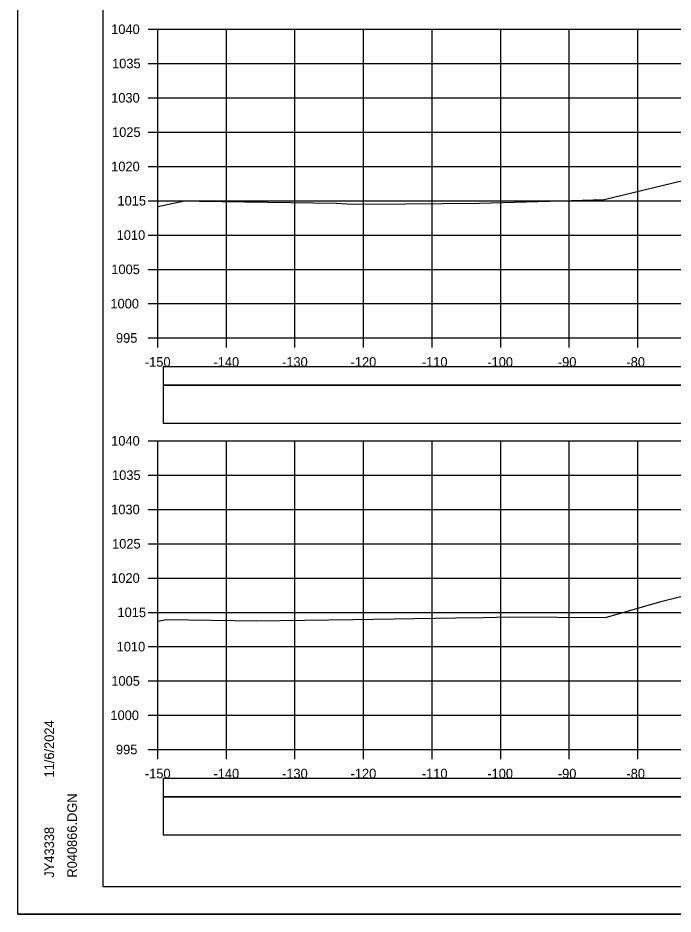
# Model space of a CAD drawing. Extents: x 1370565 to 1374448, y 301010 to 304637.
# Drawn here: x 1370564.6 to 1370660.2, y 302503.9 to 302634.5 of the extents above; entities that cross this region are included whole.
import ezdxf

# ---------------------------------------------------------------- set-up
doc = ezdxf.new("R2010")
doc.units = 0
for name, color, linetype in [('R_Axis', 7, 'Continuous'), ('R_Axis Annot', 7, 'Continuous'), ('R_Border', 7, 'Continuous'), ('R_Drive', 7, 'Continuous'), ('R_Exist Surface', 7, 'Continuous'), ('R_Grid', 7, 'Continuous'), ('R_No Plot', 7, 'Continuous')]:
    doc.layers.add(name, color=color, linetype=linetype)

msp = doc.modelspace()

# ---------------------------------------------------------------- linework, layer by layer
at = {"layer": 'R_Axis'}
for p, q in [((1370583.63, 302632.84), (1370585.03, 302632.84)), ((1370585.03, 302587.84), (1370585.03, 302632.84)), ((1370583.63, 302627.84), (1370585.03, 302627.84)), ((1370583.63, 302622.84), (1370585.03, 302622.84)), ((1370583.63, 302617.84), (1370585.03, 302617.84)), ((1370583.63, 302612.84), (1370585.03, 302612.84)), ((1370583.63, 302607.84), (1370585.03, 302607.84)), ((1370583.63, 302602.84), (1370585.03, 302602.84)), ((1370583.63, 302597.84), (1370585.03, 302597.84)), ((1370583.63, 302592.84), (1370585.03, 302592.84)), ((1370583.63, 302587.84), (1370585.03, 302587.84)), ((1370585.03, 302587.84), (1370885.03, 302587.84)), ((1370585.03, 302586.44), (1370585.03, 302587.84)), ((1370595.03, 302586.44), (1370595.03, 302587.84)), ((1370605.03, 302586.44), (1370605.03, 302587.84)), ((1370615.03, 302586.44), (1370615.03, 302587.84)), ((1370625.03, 302586.44), (1370625.03, 302587.84)), ((1370635.03, 302586.44), (1370635.03, 302587.84)), ((1370645.03, 302586.44), (1370645.03, 302587.84)), ((1370655.03, 302586.44), (1370655.03, 302587.84)), ((1370583.63, 302572.84), (1370585.03, 302572.84)), ((1370585.03, 302527.84), (1370585.03, 302572.84)), ((1370583.63, 302567.84), (1370585.03, 302567.84)), ((1370583.63, 302562.84), (1370585.03, 302562.84)), ((1370583.63, 302557.84), (1370585.03, 302557.84)), ((1370583.63, 302552.84), (1370585.03, 302552.84)), ((1370583.63, 302547.84), (1370585.03, 302547.84)), ((1370583.63, 302542.84), (1370585.03, 302542.84)), ((1370583.63, 302537.84), (1370585.03, 302537.84)), ((1370583.63, 302532.84), (1370585.03, 302532.84)), ((1370583.63, 302527.84), (1370585.03, 302527.84)), ((1370585.03, 302527.84), (1370885.03, 302527.84)), ((1370585.03, 302526.44), (1370585.03, 302527.84)), ((1370595.03, 302526.44), (1370595.03, 302527.84)), ((1370605.03, 302526.44), (1370605.03, 302527.84)), ((1370615.03, 302526.44), (1370615.03, 302527.84)), ((1370625.03, 302526.44), (1370625.03, 302527.84)), ((1370635.03, 302526.44), (1370635.03, 302527.84)), ((1370645.03, 302526.44), (1370645.03, 302527.84)), ((1370655.03, 302526.44), (1370655.03, 302527.84))]:
    msp.add_line(p, q, dxfattribs=at)
at = {"layer": 'R_Border'}
for p, q in [((1370577.03, 302507.84), (1370577.03, 302713.3)), ((1370577.03, 302507.84), (1370577.03, 302507.84)), ((1370893.21, 302507.84), (1370577.03, 302507.84))]:
    msp.add_line(p, q, dxfattribs=at)
at = {"layer": 'R_Drive'}
for points in [[(1370585.82, 302580.94), (1370884.24, 302580.94), (1370884.24, 302583.64), (1370585.82, 302583.64)], [(1370585.82, 302575.41), (1370884.24, 302575.41), (1370884.24, 302580.94), (1370585.82, 302580.94)], [(1370585.82, 302520.94), (1370884.24, 302520.94), (1370884.24, 302523.64), (1370585.82, 302523.64)], [(1370585.82, 302515.41), (1370884.24, 302515.41), (1370884.24, 302520.94), (1370585.82, 302520.94)]]:
    msp.add_lwpolyline(points, close=True, dxfattribs=at)
at = {"layer": 'R_Exist Surface'}
for points in [[(1370585.03, 302607.01), (1370587.06, 302607.44), (1370588.94, 302607.81), (1370591.05, 302607.79), (1370611.09, 302607.51), (1370613.39, 302607.35), (1370621.13, 302607.39), (1370631.95, 302607.5), (1370642.13, 302607.78), (1370650.1, 302608), (1370677.49, 302614.63)], [(1370585.03, 302546.55), (1370586.29, 302546.81), (1370599.39, 302546.62), (1370613.47, 302546.81), (1370628.47, 302547.05), (1370632.46, 302547.09), (1370636.36, 302547.2), (1370650.31, 302547.1), (1370658.59, 302549.49), (1370662.48, 302550.42)]]:
    msp.add_lwpolyline(points, dxfattribs=at)
at = {"layer": 'R_Grid'}
for p, q in [((1370585.03, 302632.84), (1370885.03, 302632.84)), ((1370585.03, 302587.84), (1370585.03, 302632.84)), ((1370595.03, 302587.84), (1370595.03, 302632.84)), ((1370605.03, 302587.84), (1370605.03, 302632.84)), ((1370615.03, 302587.84), (1370615.03, 302632.84)), ((1370625.03, 302587.84), (1370625.03, 302632.84)), ((1370635.03, 302587.84), (1370635.03, 302632.84)), ((1370645.03, 302587.84), (1370645.03, 302632.84)), ((1370655.03, 302587.84), (1370655.03, 302632.84)), ((1370585.03, 302627.84), (1370885.03, 302627.84)), ((1370585.03, 302622.84), (1370885.03, 302622.84)), ((1370585.03, 302617.84), (1370885.03, 302617.84)), ((1370585.03, 302612.84), (1370885.03, 302612.84)), ((1370585.03, 302607.84), (1370885.03, 302607.84)), ((1370585.03, 302602.84), (1370885.03, 302602.84)), ((1370585.03, 302597.84), (1370885.03, 302597.84)), ((1370585.03, 302592.84), (1370885.03, 302592.84)), ((1370585.03, 302587.84), (1370885.03, 302587.84)), ((1370585.03, 302572.84), (1370885.03, 302572.84)), ((1370585.03, 302527.84), (1370585.03, 302572.84)), ((1370595.03, 302527.84), (1370595.03, 302572.84)), ((1370605.03, 302527.84), (1370605.03, 302572.84)), ((1370615.03, 302527.84), (1370615.03, 302572.84)), ((1370625.03, 302527.84), (1370625.03, 302572.84)), ((1370635.03, 302527.84), (1370635.03, 302572.84)), ((1370645.03, 302527.84), (1370645.03, 302572.84)), ((1370655.03, 302527.84), (1370655.03, 302572.84)), ((1370585.03, 302567.84), (1370885.03, 302567.84)), ((1370585.03, 302562.84), (1370885.03, 302562.84)), ((1370585.03, 302557.84), (1370885.03, 302557.84)), ((1370585.03, 302552.84), (1370885.03, 302552.84)), ((1370585.03, 302547.84), (1370885.03, 302547.84)), ((1370585.03, 302542.84), (1370885.03, 302542.84)), ((1370585.03, 302537.84), (1370885.03, 302537.84)), ((1370585.03, 302532.84), (1370885.03, 302532.84)), ((1370585.03, 302527.84), (1370885.03, 302527.84))]:
    msp.add_line(p, q, dxfattribs=at)
at = {"layer": 'R_No Plot'}
msp.add_line((1370564.63, 302503.86), (1370897.96, 302503.86), dxfattribs=at)
for points in [[(1370564.62, 302717.2), (1370897.96, 302717.2), (1370897.96, 302503.86), (1370564.62, 302503.86)], [(1370810.95, 302713.3), (1370830.57, 302713.3), (1370830.57, 302703.42), (1370846.68, 302703.42), (1370869.88, 302703.42), (1370869.88, 302670.75), (1370893.09, 302670.75), (1370893.21, 302507.84), (1370577.03, 302507.84), (1370577.03, 302713.3)]]:
    msp.add_lwpolyline(points, close=True, dxfattribs=at)

# ---------------------------------------------------------------- texts
at = {"layer": 'R_Axis Annot'}
for s, p in [('1040', (1370578.22, 302632.14)), ('1035', (1370578.35, 302627.14)), ('1030', (1370578.22, 302622.14)), ('1025', (1370578.35, 302617.14)), ('1020', (1370578.22, 302612.14)), ('1015', (1370579.14, 302607.14)), ('1010', (1370579.02, 302602.14)), ('1005', (1370578.24, 302597.14)), ('1000', (1370578.11, 302592.14)), ('995', (1370578.92, 302587.14)), ('-150', (1370583.14, 302583.64)), ('-140', (1370593.14, 302583.64)), ('-130', (1370603.14, 302583.64)), ('-120', (1370613.14, 302583.64)), ('-110', (1370623.53, 302583.64)), ('-100', (1370633.08, 302583.64)), ('-90', (1370643.37, 302583.64)), ('-80', (1370653.37, 302583.64)), ('1040', (1370578.22, 302572.14)), ('1035', (1370578.35, 302567.14)), ('1030', (1370578.22, 302562.14)), ('1025', (1370578.35, 302557.14)), ('1020', (1370578.22, 302552.14)), ('1015', (1370579.14, 302547.14)), ('1010', (1370579.02, 302542.14)), ('1005', (1370578.24, 302537.14)), ('1000', (1370578.11, 302532.14)), ('995', (1370578.92, 302527.14)), ('-150', (1370583.14, 302523.64)), ('-140', (1370593.14, 302523.64)), ('-130', (1370603.14, 302523.64)), ('-120', (1370613.14, 302523.64)), ('-110', (1370623.53, 302523.64)), ('-100', (1370633.08, 302523.64)), ('-90', (1370643.37, 302523.64)), ('-80', (1370653.37, 302523.64))]:
    msp.add_text(s, height=1.4, dxfattribs=at).set_placement(p)
at = {"layer": 'R_Border'}
for s, p in [('11/6/2024', (1370569.89, 302523.77)), ('R040866.DGN', (1370573.22, 302509.17)), ('JY43338', (1370569.89, 302509.17))]:
    msp.add_text(s, height=1.4, rotation=90, dxfattribs=at).set_placement(p)

doc.saveas('drawing.dxf')
